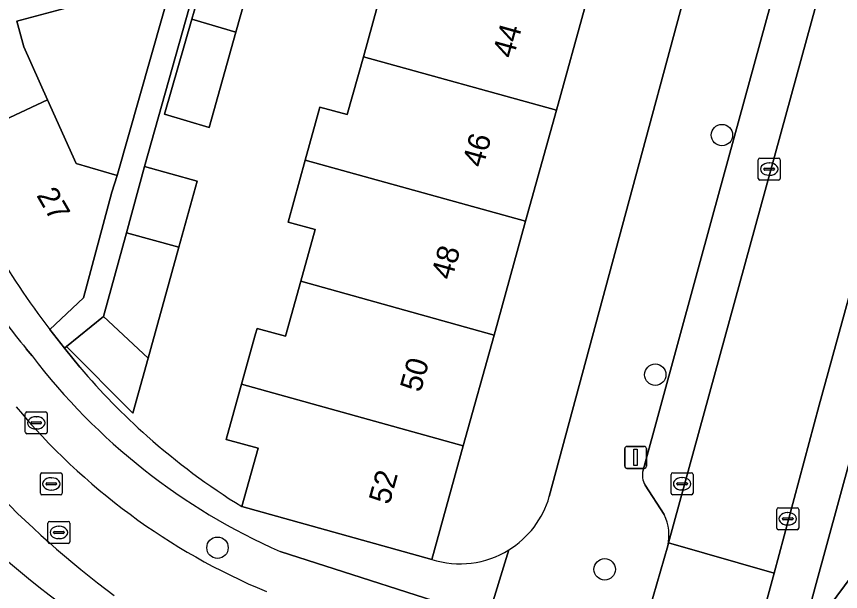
# Model space of a CAD drawing. Extents: x 162542 to 163147, y 380779 to 381521.
# Drawn here: x 163054.79 to 163092.41, y 381021.08 to 381047.33 of the extents above; entities that cross this region are included whole.
import ezdxf

# ---------------------------------------------------------------- set-up
doc = ezdxf.new("R2010")
doc.units = 0
for name, color, linetype in [('IMGEO_Berm_groen', 7, 'Continuous'), ('IMGEO_Boom', 7, 'Continuous'), ('IMGEO_Erf', 7, 'Continuous'), ('IMGEO_Kolk', 7, 'Continuous'), ('IMGEO_Lichtmast', 7, 'Continuous'), ('IMGEO_Muur', 7, 'Continuous'), ('IMGEO_Pand', 7, 'Continuous'), ('IMGEO_Pand_nummerreeks', 7, 'Continuous'), ('IMGEO_Parkeervlak_open', 7, 'Continuous'), ('IMGEO_Rijbaan_lokaal_open', 7, 'Continuous'), ('IMGEO_Rioolput', 7, 'Continuous'), ('IMGEO_Voetpad_open', 7, 'Continuous')]:
    doc.layers.add(name, color=color, linetype=linetype)

msp = doc.modelspace()

# ---------------------------------------------------------------- linework, layer by layer
at = {"layer": 'IMGEO_Berm_groen'}
for points in [[(163109.3, 381087.086), (163093.379, 381029.068), (163091.294, 381021.437), (163090.379, 381018.056), (163091.195, 381019.449), (163095.086, 381024.701), (163097.994, 381027.705), (163100.091, 381030.633), (163101.545, 381033.297), (163102.955, 381036.558), (163113.57, 381075.334)], [(163119.028, 381077.818), (163119.528, 381080.672), (163115.4, 381081.696), (163115.317, 381081.716), (163113.57, 381075.334), (163102.955, 381036.558), (163101.545, 381033.297), (163100.091, 381030.633), (163097.994, 381027.705), (163095.086, 381024.701), (163091.195, 381019.449), (163090.379, 381018.056), (163089.453, 381014.635), (163089.416, 381014.332), (163089.57, 381012.554), (163089.809, 381011.641), (163090.516, 381010.104), (163095.768, 381008.68)]]:
    msp.add_lwpolyline(points, dxfattribs=at)
at = {"layer": 'IMGEO_Boom'}
for centre in [(163086.994, 381041.913), (163083.949, 381030.975), (163063.965, 381023.073), (163081.642, 381022.087)]:
    msp.add_circle(centre, 0.489, dxfattribs=at)
at = {"layer": 'IMGEO_Erf'}
for points in [[(163079.113, 381025.409), (163089.044, 381062.198), (163093.539, 381078.503), (163098.537, 381095.857)], [(163093.75, 381094.611), (163092.295, 381089.37), (163090.84, 381084.129), (163089.386, 381078.888), (163087.931, 381073.647), (163086.476, 381068.406), (163085.001, 381063.092), (163083.577, 381057.961), (163082.192, 381052.974), (163080.799, 381047.953), (163079.436, 381043.045), (163078.029, 381037.977), (163076.589, 381032.786), (163075.182, 381027.72), (163073.745, 381022.542)], [(163063.488, 381054.525), (163061.026, 381055.283), (163062.072, 381058.682), (163063.117, 381062.081), (163065.835, 381062.155), (163066.389, 381071.067), (163067.876, 381070.6), (163067.083, 381068.079), (163066.935, 381062.854), (163060.637, 381040.472), (163063.038, 381039.816), (163062.2, 381036.793), (163060.796, 381031.727), (163060.101, 381029.218), (163057.078, 381032.257), (163056.987, 381032.183), (163057.677, 381031.311)], [(163057.769, 381047.906), (163054.809, 381047.109), (163055.123, 381045.939), (163056.205, 381043.521), (163057.506, 381040.614), (163059.38, 381040.076), (163063.488, 381054.525)], [(163065.074, 381024.953), (163065.814, 381027.613), (163064.36, 381028.018), (163065.061, 381030.539), (163065.7, 381032.836), (163065.769, 381033.086), (163067.064, 381032.727), (163067.763, 381035.244), (163068.418, 381037.599), (163067.184, 381037.942), (163067.97, 381040.773), (163068.643, 381043.194), (163069.892, 381042.847), (163070.628, 381045.494), (163071.272, 381047.811)]]:
    msp.add_lwpolyline(points, dxfattribs=at)
msp.add_lwpolyline([(163062.797, 381047.202), (163063.966, 381051.246), (163065.341, 381056.001), (163066.613, 381060.403), (163068.526, 381059.871), (163067.287, 381055.46), (163065.941, 381050.665), (163064.804, 381046.617), (163063.583, 381042.267), (163061.543, 381042.862)], close=True, dxfattribs=at)
for centre, radius, start, end in [((163082.93, 381052.956), 33.26, 220.5997, 228.1848), ((163081.509, 381051.548), 31.263, 228.4057, 238.2844), ((163075.038, 381026.585), 4.241, 301.6766, 343.9086), ((163075.035, 381026.582), 4.24, 252.293, 301.7326)]:
    msp.add_arc(centre, radius, start, end, dxfattribs=at)
at = {"layer": 'IMGEO_Kolk'}
for p, q in [((163088.729, 381040.861), (163089.581, 381040.861)), ((163088.654, 381039.935), (163088.654, 381040.787)), ((163089.142, 381040.641), (163089.167, 381040.641)), ((163089.655, 381040.787), (163089.655, 381039.935)), ((163088.913, 381040.355), (163088.913, 381040.367)), ((163089.351, 381040.318), (163088.953, 381040.318)), ((163088.956, 381040.404), (163089.354, 381040.404)), ((163089.397, 381040.367), (163089.397, 381040.355)), ((163089.581, 381039.861), (163088.729, 381039.861)), ((163089.165, 381040.081), (163089.14, 381040.081)), ((163055.192, 381028.35), (163055.192, 381029.202)), ((163055.267, 381029.276), (163056.119, 381029.276)), ((163056.193, 381029.202), (163056.193, 381028.35)), ((163055.494, 381028.819), (163055.892, 381028.819)), ((163055.68, 381029.056), (163055.705, 381029.056)), ((163055.451, 381028.77), (163055.451, 381028.782)), ((163055.889, 381028.733), (163055.491, 381028.733)), ((163055.703, 381028.496), (163055.678, 381028.496)), ((163055.935, 381028.782), (163055.935, 381028.77)), ((163056.119, 381028.276), (163055.267, 381028.276)), ((163084.675, 381025.568), (163084.675, 381026.42)), ((163084.75, 381026.494), (163085.602, 381026.494)), ((163085.163, 381026.274), (163085.188, 381026.274)), ((163085.676, 381026.42), (163085.676, 381025.568)), ((163084.934, 381025.988), (163084.934, 381026)), ((163085.372, 381025.951), (163084.974, 381025.951)), ((163084.977, 381026.037), (163085.375, 381026.037)), ((163085.418, 381026), (163085.418, 381025.988)), ((163085.602, 381025.494), (163084.75, 381025.494)), ((163085.186, 381025.714), (163085.161, 381025.714)), ((163089.496, 381023.97), (163089.496, 381024.822)), ((163089.571, 381024.896), (163090.423, 381024.896)), ((163090.497, 381024.822), (163090.497, 381023.97)), ((163089.755, 381024.39), (163089.755, 381024.402)), ((163090.193, 381024.353), (163089.795, 381024.353)), ((163089.798, 381024.439), (163090.196, 381024.439)), ((163089.984, 381024.676), (163090.009, 381024.676)), ((163090.239, 381024.402), (163090.239, 381024.39)), ((163090.007, 381024.116), (163089.982, 381024.116)), ((163090.423, 381023.896), (163089.571, 381023.896))]:
    msp.add_line(p, q, dxfattribs=at)
for points in [[(163088.729, 381040.861), (163089.581, 381040.861)], [(163088.654, 381039.935), (163088.654, 381040.787)], [(163089.655, 381040.787), (163089.655, 381039.935)], [(163089.581, 381039.861), (163088.729, 381039.861)], [(163055.192, 381028.35), (163055.192, 381029.202)], [(163055.267, 381029.276), (163056.119, 381029.276)], [(163056.193, 381029.202), (163056.193, 381028.35)], [(163056.119, 381028.276), (163055.267, 381028.276)], [(163084.675, 381025.568), (163084.675, 381026.42)], [(163084.75, 381026.494), (163085.602, 381026.494)], [(163085.676, 381026.42), (163085.676, 381025.568)], [(163085.602, 381025.494), (163084.75, 381025.494)], [(163089.496, 381023.97), (163089.496, 381024.822)], [(163089.571, 381024.896), (163090.423, 381024.896)], [(163090.497, 381024.822), (163090.497, 381023.97)], [(163090.423, 381023.896), (163089.571, 381023.896)]]:
    msp.add_lwpolyline(points, dxfattribs=at)
for centre, radius, start, end in [((163088.731, 381040.785), 0.0765, 91.552, 178.448), ((163088.731, 381040.785), 0.0765, 91.552, 178.448), ((163089.579, 381040.785), 0.0765, 1.552, 88.448), ((163089.579, 381040.785), 0.0765, 1.552, 88.448), ((163088.953, 381040.364), 0.0403, 85.8775, 175.7526), ((163088.95, 381040.354), 0.0366, 178.938, 274.7102), ((163089.354, 381040.361), 0.043, 264.8664, 352.4533), ((163089.358, 381040.366), 0.0386, 1.7309, 96.639), ((163088.731, 381039.937), 0.0765, 181.552, 268.448), ((163088.731, 381039.937), 0.0765, 181.552, 268.448), ((163089.579, 381039.937), 0.0765, 271.552, 358.448), ((163089.579, 381039.937), 0.0765, 271.552, 358.448), ((163055.269, 381029.2), 0.0765, 91.552, 178.448), ((163055.269, 381029.2), 0.0765, 91.552, 178.448), ((163056.117, 381029.2), 0.0765, 1.552, 88.448), ((163056.117, 381029.2), 0.0765, 1.552, 88.448), ((163055.491, 381028.779), 0.0403, 85.8775, 175.7526), ((163055.896, 381028.781), 0.0386, 1.7309, 96.639), ((163055.488, 381028.769), 0.0366, 178.938, 274.7102), ((163055.892, 381028.776), 0.043, 264.8664, 352.4533), ((163055.269, 381028.352), 0.0765, 181.552, 268.448), ((163055.269, 381028.352), 0.0765, 181.552, 268.448), ((163056.117, 381028.352), 0.0765, 271.552, 358.448), ((163056.117, 381028.352), 0.0765, 271.552, 358.448), ((163084.752, 381026.418), 0.0765, 91.552, 178.448), ((163084.752, 381026.418), 0.0765, 91.552, 178.448), ((163085.6, 381026.418), 0.0765, 1.552, 88.448), ((163085.6, 381026.418), 0.0765, 1.552, 88.448), ((163084.974, 381025.997), 0.0403, 85.8775, 175.7526), ((163084.971, 381025.987), 0.0366, 178.938, 274.7102), ((163085.375, 381025.994), 0.043, 264.8664, 352.4533), ((163085.379, 381025.999), 0.0386, 1.7309, 96.639), ((163084.752, 381025.57), 0.0765, 181.552, 268.448), ((163084.752, 381025.57), 0.0765, 181.552, 268.448), ((163085.6, 381025.57), 0.0765, 271.552, 358.448), ((163085.6, 381025.57), 0.0765, 271.552, 358.448), ((163089.573, 381024.82), 0.0765, 91.552, 178.448), ((163089.573, 381024.82), 0.0765, 91.552, 178.448), ((163090.421, 381024.82), 0.0765, 1.552, 88.448), ((163090.421, 381024.82), 0.0765, 1.552, 88.448), ((163089.795, 381024.399), 0.0403, 85.8775, 175.7526), ((163089.792, 381024.389), 0.0366, 178.938, 274.7102), ((163090.196, 381024.396), 0.043, 264.8664, 352.4533), ((163090.2, 381024.401), 0.0386, 1.7309, 96.639), ((163089.573, 381023.972), 0.0765, 181.552, 268.448), ((163089.573, 381023.972), 0.0765, 181.552, 268.448), ((163090.421, 381023.972), 0.0765, 271.552, 358.448), ((163090.421, 381023.972), 0.0765, 271.552, 358.448)]:
    msp.add_arc(centre, radius, start, end, dxfattribs=at)
for centre, major_axis, ratio, start_param, end_param in [((163089.141, 381040.361), (-0.387, 0.002), 0.722429, 4.712389, 7.853982), ((163089.166, 381040.361), (-0.39, 0.002), 0.717154, 1.570796, 4.712389), ((163055.679, 381028.776), (-0.387, 0.002), 0.722429, 4.712389, 7.853982), ((163055.704, 381028.776), (-0.39, 0.002), 0.717154, 1.570796, 4.712389), ((163085.162, 381025.994), (-0.387, 0.002), 0.722429, 4.712389, 7.853982), ((163085.187, 381025.994), (-0.39, 0.002), 0.717154, 1.570796, 4.712389), ((163089.983, 381024.396), (-0.387, 0.002), 0.722429, 4.712389, 7.853982), ((163090.008, 381024.396), (-0.39, 0.002), 0.717154, 1.570796, 4.712389)]:
    msp.add_ellipse(centre, major_axis=major_axis, ratio=ratio, start_param=start_param, end_param=end_param, dxfattribs=at)
at = {"layer": 'IMGEO_Lichtmast'}
for p, q in [((163082.655, 381027.699), (163083.445, 381027.699)), ((163083.445, 381027.699), (163082.655, 381027.699)), ((163082.555, 381026.799), (163082.555, 381027.599)), ((163082.555, 381027.599), (163082.555, 381026.799)), ((163083.545, 381027.599), (163083.545, 381026.799)), ((163083.545, 381026.799), (163083.545, 381027.599)), ((163083.445, 381026.699), (163082.655, 381026.699)), ((163082.655, 381026.699), (163083.445, 381026.699))]:
    msp.add_line(p, q, dxfattribs=at)
msp.add_lwpolyline([(163082.975, 381027.574), (163083.125, 381027.574), (163083.125, 381026.824), (163082.975, 381026.824), (163082.975, 381027.574)], dxfattribs=at)
for centre, start, end in [((163082.655, 381027.599), 90, 180), ((163082.655, 381027.599), 90, 180), ((163083.445, 381027.599), 0, 90), ((163083.445, 381027.599), 360, 90), ((163082.655, 381026.799), 180, 270), ((163082.655, 381026.799), 180, 270), ((163083.445, 381026.799), 270, 0), ((163083.445, 381026.799), 270, 0)]:
    msp.add_arc(centre, 0.1, start, end, dxfattribs=at)
at = {"layer": 'IMGEO_Muur'}
msp.add_arc((163081.509, 381051.548), 31.263, 228.4057, 238.2844, dxfattribs=at)
at = {"layer": 'IMGEO_Pand'}
for points in [[(163062.797, 381047.202), (163064.804, 381046.617), (163065.941, 381050.665), (163063.966, 381051.246)], [(163070.628, 381045.494), (163079.436, 381043.045), (163080.799, 381047.953), (163070.735, 381050.75), (163070.015, 381048.16), (163071.272, 381047.811)], [(163062.797, 381047.202), (163061.543, 381042.862), (163063.583, 381042.267), (163064.804, 381046.617)], [(163078.029, 381037.977), (163079.436, 381043.045), (163070.628, 381045.494), (163069.892, 381042.847), (163068.643, 381043.194), (163067.97, 381040.773)], [(163067.763, 381035.244), (163076.589, 381032.786), (163078.029, 381037.977), (163067.97, 381040.773), (163067.184, 381037.942), (163068.418, 381037.599)], [(163060.637, 381040.472), (163059.814, 381037.458), (163062.2, 381036.793), (163063.038, 381039.816)], [(163062.2, 381036.793), (163059.814, 381037.458), (163058.766, 381033.624), (163060.796, 381031.727)], [(163067.763, 381035.244), (163067.064, 381032.727), (163065.769, 381033.086), (163065.7, 381032.836), (163065.061, 381030.539), (163075.182, 381027.72), (163076.589, 381032.786)], [(163060.796, 381031.727), (163058.766, 381033.624), (163057.078, 381032.257), (163060.101, 381029.218)], [(163075.182, 381027.72), (163065.061, 381030.539), (163064.36, 381028.018), (163065.814, 381027.613), (163065.074, 381024.953), (163073.745, 381022.542)]]:
    msp.add_lwpolyline(points, close=True, dxfattribs=at)
for points in [[(163051.514, 381041.335), (163056.205, 381043.521), (163055.123, 381045.939), (163054.809, 381047.109), (163057.769, 381047.906), (163057.047, 381050.598), (163056.978, 381050.855), (163049.176, 381048.749), (163049.201, 381048.656), (163050.016, 381045.64)], [(163056.307, 381033.042), (163057.851, 381034.483), (163059.139, 381039.315), (163059.38, 381040.076), (163057.506, 381040.614), (163056.205, 381043.521), (163051.514, 381041.335)]]:
    msp.add_lwpolyline(points, dxfattribs=at)
for centre, radius, start, end in [((163086.063, 381055.771), 37.444, 202.6775, 217.3746), ((163086.478, 381056.051), 47.846, 223.3092, 229.3672)]:
    msp.add_arc(centre, radius, start, end, dxfattribs=at)
at = {"layer": 'IMGEO_Parkeervlak_open'}
for points in [[(163100.631, 381089.497), (163100.487, 381088.976), (163086.585, 381038.264), (163083.391, 381026.615)], [(163084.522, 381023.155), (163084.559, 381023.291), (163102.722, 381089.551)], [(163107.568, 381088.303), (163098.85, 381056.569), (163093.215, 381036.056), (163091.439, 381029.59), (163089.373, 381021.916), (163087.365, 381014.541), (163086.271, 381010.462), (163085.179, 381006.534), (163084.668, 381004.939)], [(163087.092, 381006.049), (163088.512, 381011.194), (163089.294, 381014.047), (163089.453, 381014.635), (163090.379, 381018.056), (163091.294, 381021.437), (163093.379, 381029.068), (163109.3, 381087.086)], [(163055.5, 381031.83), (163055.32, 381032.056), (163055.232, 381032.162)], [(163083.484, 381025.93), (163084.362, 381024.584)], [(163076.311, 381019.863), (163066.831, 381022.9)]]:
    msp.add_lwpolyline(points, dxfattribs=at)
for centre, radius, start, end in [((163081.644, 381054.027), 41.699, 193.8786, 246.6377), ((163082.621, 381054.882), 35.586, 214.5046, 219.6776), ((163087.428, 381058.417), 46.931, 214.2394, 233.0996), ((163078.527, 381049.395), 28.962, 217.3359, 246.1806), ((163077.641, 381048.539), 29.753, 219.7527, 247.3802), ((163084.323, 381026.393), 0.958, 166.5902, 208.873), ((163082.389, 381023.64), 2.187, 347.2002, 25.577)]:
    msp.add_arc(centre, radius, start, end, dxfattribs=at)
at = {"layer": 'IMGEO_Rijbaan_lokaal_open'}
msp.add_lwpolyline([(163107.568, 381088.303), (163103.434, 381089.372), (163102.722, 381089.551), (163084.559, 381023.291), (163089.373, 381021.916), (163091.439, 381029.59), (163093.215, 381036.056), (163098.85, 381056.569)], close=True, dxfattribs=at)
for points in [[(163089.373, 381021.916), (163084.559, 381023.291), (163084.522, 381023.155), (163083.684, 381020.268)], [(163080.215, 381007.669), (163079.872, 381006.55), (163084.668, 381004.939), (163085.179, 381006.534), (163086.271, 381010.462), (163087.365, 381014.541), (163089.373, 381021.916)]]:
    msp.add_lwpolyline(points, dxfattribs=at)
for centre, radius, start, end in [((163087.428, 381058.417), 46.931, 214.2394, 233.0996), ((163077.641, 381048.539), 29.753, 219.7527, 247.3802)]:
    msp.add_arc(centre, radius, start, end, dxfattribs=at)
at = {"layer": 'IMGEO_Rioolput'}
for p, q in [((163055.878, 381025.562), (163055.878, 381026.414)), ((163055.953, 381026.488), (163056.805, 381026.488)), ((163056.366, 381026.268), (163056.391, 381026.268)), ((163056.879, 381026.414), (163056.879, 381025.562)), ((163056.137, 381025.982), (163056.137, 381025.994)), ((163056.575, 381025.945), (163056.177, 381025.945)), ((163056.18, 381026.031), (163056.578, 381026.031)), ((163056.621, 381025.994), (163056.621, 381025.982)), ((163056.805, 381025.488), (163055.953, 381025.488)), ((163056.389, 381025.708), (163056.364, 381025.708)), ((163056.224, 381023.346), (163056.224, 381024.198)), ((163056.299, 381024.272), (163057.151, 381024.272)), ((163056.712, 381024.052), (163056.737, 381024.052)), ((163057.225, 381024.198), (163057.225, 381023.346)), ((163056.483, 381023.766), (163056.483, 381023.778)), ((163056.921, 381023.729), (163056.523, 381023.729)), ((163056.526, 381023.815), (163056.924, 381023.815)), ((163056.967, 381023.778), (163056.967, 381023.766)), ((163057.151, 381023.272), (163056.299, 381023.272)), ((163056.735, 381023.492), (163056.71, 381023.492))]:
    msp.add_line(p, q, dxfattribs=at)
for points in [[(163055.878, 381025.562), (163055.878, 381026.414)], [(163055.953, 381026.488), (163056.805, 381026.488)], [(163056.879, 381026.414), (163056.879, 381025.562)], [(163056.805, 381025.488), (163055.953, 381025.488)], [(163056.224, 381023.346), (163056.224, 381024.198)], [(163056.299, 381024.272), (163057.151, 381024.272)], [(163057.225, 381024.198), (163057.225, 381023.346)], [(163057.151, 381023.272), (163056.299, 381023.272)]]:
    msp.add_lwpolyline(points, dxfattribs=at)
for centre, radius, start, end in [((163055.955, 381026.412), 0.0765, 91.552, 178.448), ((163055.955, 381026.412), 0.0765, 91.552, 178.448), ((163056.803, 381026.412), 0.0765, 1.552, 88.448), ((163056.803, 381026.412), 0.0765, 1.552, 88.448), ((163056.177, 381025.991), 0.0403, 85.8775, 175.7526), ((163056.174, 381025.981), 0.0366, 178.938, 274.7102), ((163056.578, 381025.988), 0.043, 264.8664, 352.4533), ((163056.582, 381025.993), 0.0386, 1.7309, 96.639), ((163055.955, 381025.564), 0.0765, 181.552, 268.448), ((163055.955, 381025.564), 0.0765, 181.552, 268.448), ((163056.803, 381025.564), 0.0765, 271.552, 358.448), ((163056.803, 381025.564), 0.0765, 271.552, 358.448), ((163056.301, 381024.196), 0.0765, 91.552, 178.448), ((163056.301, 381024.196), 0.0765, 91.552, 178.448), ((163057.149, 381024.196), 0.0765, 1.552, 88.448), ((163057.149, 381024.196), 0.0765, 1.552, 88.448), ((163056.523, 381023.775), 0.0403, 85.8775, 175.7526), ((163056.52, 381023.765), 0.0366, 178.938, 274.7102), ((163056.924, 381023.772), 0.043, 264.8664, 352.4533), ((163056.928, 381023.777), 0.0386, 1.7309, 96.639), ((163056.301, 381023.348), 0.0765, 181.552, 268.448), ((163056.301, 381023.348), 0.0765, 181.552, 268.448), ((163057.149, 381023.348), 0.0765, 271.552, 358.448), ((163057.149, 381023.348), 0.0765, 271.552, 358.448)]:
    msp.add_arc(centre, radius, start, end, dxfattribs=at)
for centre, major_axis, ratio, start_param, end_param in [((163056.365, 381025.988), (-0.387, 0.002), 0.722429, 4.712389, 7.853982), ((163056.39, 381025.988), (-0.39, 0.002), 0.717154, 1.570796, 4.712389), ((163056.711, 381023.772), (-0.387, 0.002), 0.722429, 4.712389, 7.853982), ((163056.736, 381023.772), (-0.39, 0.002), 0.717154, 1.570796, 4.712389)]:
    msp.add_ellipse(centre, major_axis=major_axis, ratio=ratio, start_param=start_param, end_param=end_param, dxfattribs=at)
at = {"layer": 'IMGEO_Voetpad_open'}
for points in [[(163116.374, 381139.268), (163105.933, 381138.5), (163105.012, 381135.183), (163107.841, 381134.207), (163108.43, 381133.686), (163108.607, 381132.594), (163098.537, 381095.857), (163093.539, 381078.503), (163089.044, 381062.198), (163079.113, 381025.409)], [(163083.391, 381026.615), (163086.585, 381038.264), (163100.487, 381088.976), (163100.631, 381089.497)], [(163057.677, 381031.311), (163056.987, 381032.183), (163056.307, 381033.042)], [(163055.232, 381032.162), (163055.32, 381032.056), (163055.5, 381031.83)], [(163084.362, 381024.584), (163083.484, 381025.93)], [(163073.745, 381022.542), (163065.074, 381024.953)], [(163066.831, 381022.9), (163076.311, 381019.863), (163077.265, 381022.975)], [(163077.265, 381022.975), (163076.311, 381019.863)], [(163083.684, 381020.268), (163084.522, 381023.155)]]:
    msp.add_lwpolyline(points, dxfattribs=at)
msp.add_lwpolyline([(163066.935, 381062.854), (163067.083, 381068.079), (163067.876, 381070.6), (163066.389, 381071.067), (163065.835, 381062.155), (163064.534, 381057.924), (163063.488, 381054.525), (163059.38, 381040.076), (163059.139, 381039.315), (163057.851, 381034.483), (163056.307, 381033.042), (163056.987, 381032.183), (163057.078, 381032.257), (163058.766, 381033.624), (163059.814, 381037.458), (163060.637, 381040.472)], close=True, dxfattribs=at)
for centre, radius, start, end in [((163081.644, 381054.027), 41.699, 193.8786, 246.6377), ((163086.063, 381055.771), 37.444, 202.6775, 217.3746), ((163082.621, 381054.882), 35.586, 214.5046, 219.6776), ((163078.527, 381049.395), 28.962, 217.3359, 246.1806), ((163082.93, 381052.956), 33.26, 220.5997, 228.1848), ((163081.509, 381051.548), 31.263, 228.4057, 238.2844), ((163084.323, 381026.393), 0.958, 166.5902, 208.873), ((163075.038, 381026.585), 4.241, 301.6766, 343.9086), ((163082.389, 381023.64), 2.187, 347.2002, 25.577), ((163086.478, 381056.051), 47.846, 223.3092, 229.3672), ((163075.035, 381026.582), 4.24, 252.293, 301.7326)]:
    msp.add_arc(centre, radius, start, end, dxfattribs=at)

# ---------------------------------------------------------------- texts
at = {"layer": 'IMGEO_Pand_nummerreeks'}
for s, rotation, p in [('44', 74.4862, (163077.468, 381045.377)), ('46', 74.4862, (163076.084, 381040.389)), ('27', 300.0244, (163055.679, 381039.165)), ('48', 74.4907, (163074.661, 381035.262)), ('50', 74.4782, (163073.237, 381030.134)), ('52', 74.4896, (163071.813, 381025.005))]:
    msp.add_text(s, height=1, rotation=rotation, dxfattribs=at).set_placement(p)

doc.saveas('drawing.dxf')
